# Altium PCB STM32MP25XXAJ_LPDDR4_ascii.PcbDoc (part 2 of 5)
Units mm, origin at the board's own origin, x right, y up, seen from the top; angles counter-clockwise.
Board outline 172 x 137 mm, 4 copper layers (Top Layer, Signal Layer 1, Signal Layer 2, Bottom Layer), stack 1.614 mm thick; 188 components, 294 nets, 1141 pads, 872 vias.
Unrouted connection lines stored in the file: 13.
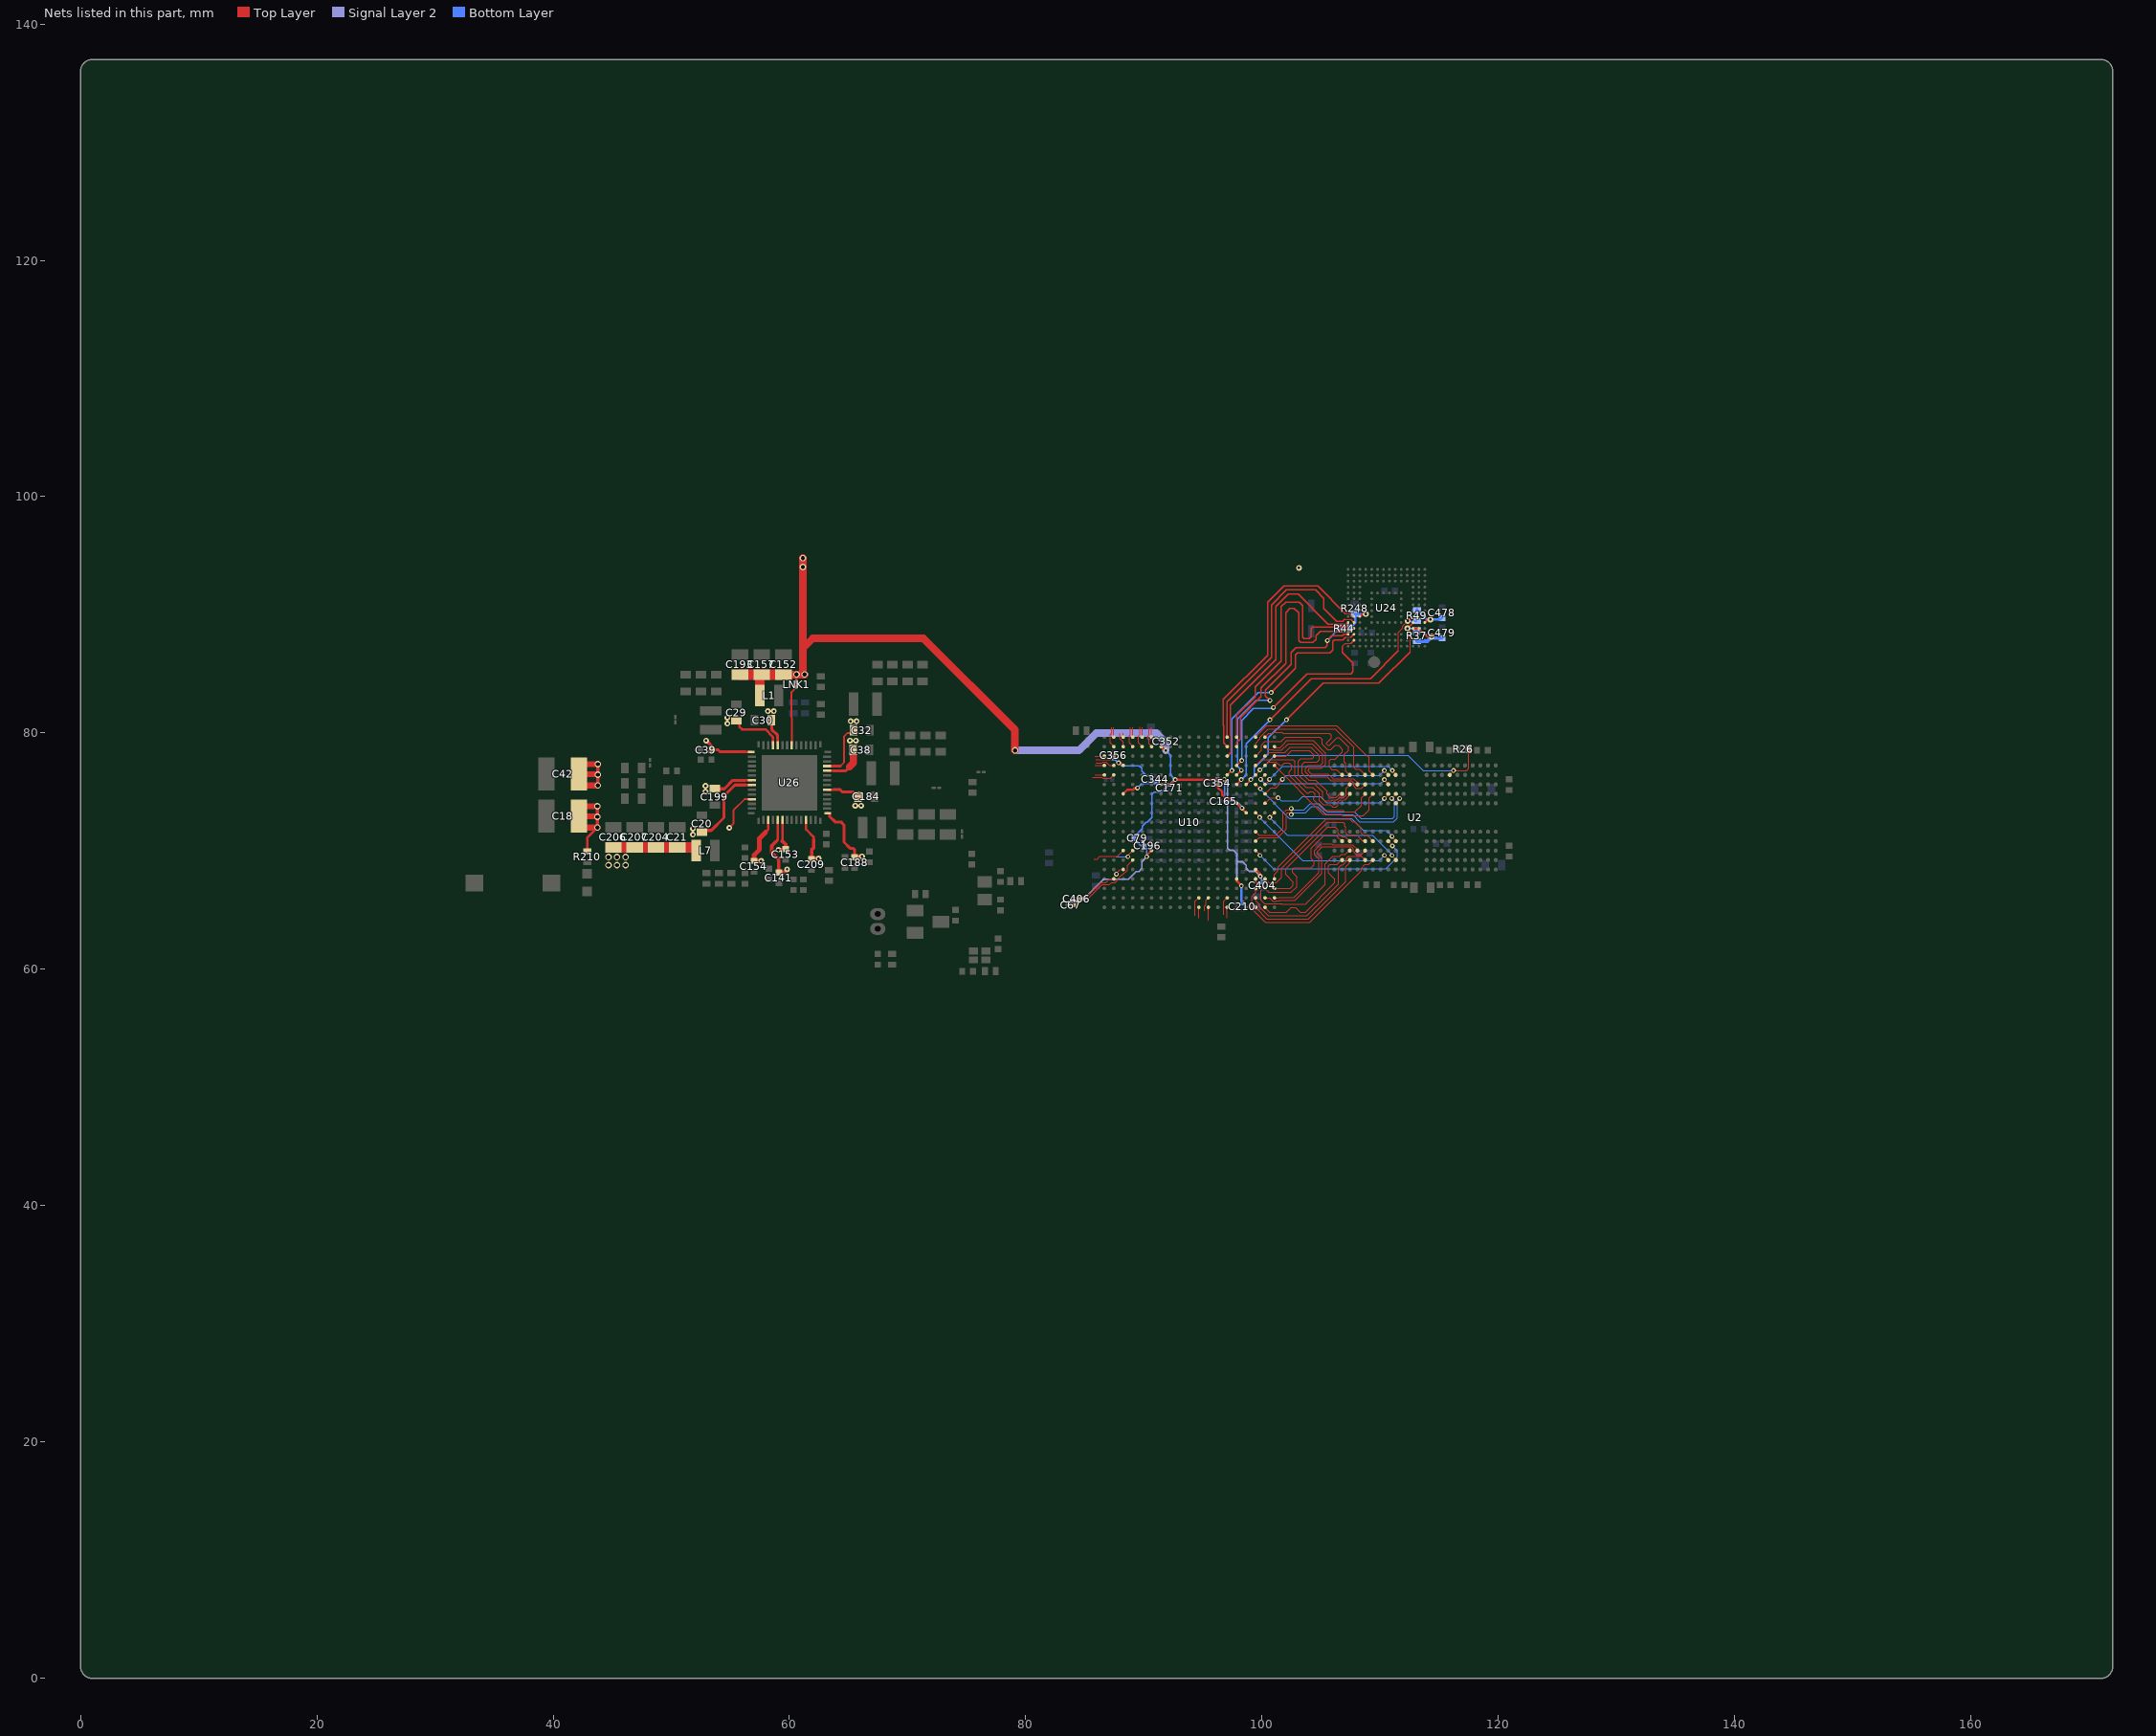
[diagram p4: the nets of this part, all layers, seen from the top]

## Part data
B2: library part MCD-03492, "Switch tactile, SPST-NO, 50mA, 12V, 6x3.8mm"
C18 C42: library part MCD-01796, "Capacitor, Tantalum, 100uF, 6V3, 40mR, +/-20%,  Type_B (3528 metric), T=1.9mm"
C19 C21 C152 C157 C186 C187 C193 C204 C206 C207: library part MCD-03139, "Capacitor, MLCC, 22uF, 10V, X5R, +/-20%, 0805, T=1,25mm"
C20 C29 C30 C32 C38 C184 C199: library part MCD-00099, "Capacitor, MLCC, 10uF, 10V, X5R, +/-10%, 0603, T=0,8mm"
C22 C23 C24 C26 C27 C28 C34 C35 C36 C37 C41 C183 C200 C202: library part MCD-00100, "Capacitor, MLCC, 22uF, 6V3, X5R, +/-20%, 0603, T=0,8mm"
C33: library part MCD-00011, "Capacitor, MLCC, 10nF, 16V, X7R, 10%, 0402, T=0.5mm"
C39 C43 C153 C154 C188: library part MCD-00095, "Capacitor, MLCC, 1uF, 25V, X5R, +/-10%, 0402, T=0.5mm"
C40: library part MCD-03140, "Capacitor, MLCC, 10uF, 6.3V, X5R, +/-20%, 0402, T=0.5mm"
C50 C51 C62 C63: library part MCD-01341, "Capacitor, MLCC, 10uF, 6V3, X5R, +/-20%, 0603, T=0.8mm"
C52 C53 C54 C55 C56 C57 C58 C59 C60 C61 C64 C65 C66 C68 C177 C182 C267 C479: library part MCD-00006, "Capacitor, MLCC, 100nF, 16V, X7R, +/-10%, 0402, T=0.5mm"
C67 C159 C163 C164 C166 C167 C168 C169 C173 C174 C175 C176 C191 C192 C195 C201 C360 C372 C377 C378 C380 C381 C382 C383 C386 C387 C388 C389 C390 C399 C400 C402: library part MCD-02377, "Capacitor, MLCC, 1uF, 6.3V, X5R, +/-20%, 0201, T=0,3mm"
C79: library part MCD-02235, "Capacitor, MLCC, 2.2uF, 10V, X5R,+/-10%, 0201, T=0.5mm"
C81 C86 C90 C92: library part MCD-00674, "Capacitor, MLCC, 6.8pF, 50V, NPO, +-0.25pF, 0402, T=0.5mm"
C87: library part MCD-00006, "Capacitor,100nF,16V,X7R,10%,0402"
C88: library part MCD-01823, "Capacitor, MLCC, 2.2uF, 6V3, X5R,+/-10%, 0402, T=0.5mm"
C91 C141 C142 C156 C189 C190 C208 C209 C217: library part MCD-01356, "Capacitor, MLCC, 4.7uF, 6V3, X5R, +/-20%, 0402, T=0.5mm"
C143 C161 C165 C171 C196 C210 C342 C344 C352 C353 C354 C355 C356 C357 C393 C404 C406 C407 C408 C409 C417: library part MCD-01535, "Capacitor, MLCC,100nF, 10V, X7R, +/-10%, 0201, T=0.3mm"
C155: library part MCD-02198, "Capacitor, MLCC, 10nF, 50V, X7R, +/-10%, 0402, T=0.5mm"
C180 C478 C481: library part MCD-02606, "Capacitor, MLCC, 2.2uF, 6.3V, X5R, +/-10%, 0402, T=0.5mm"
C384: library part MCD-01534, "Capacitor, MLCC, 4,7uF, 6V3, X5R, +/-20%, 0201, T=0.5mm"
CN12: library part MCD-00655, "Header 2 circuits, 1.25mm Pitch ,  Vertical, with Friction Lock"
D5: library part MCD-00034
D6: library part MCD-03280, "Diode, Schottky, Dual Common Cathode, 0V3, 300mA, 40V, SOT-23"
L1 L6: library part MCD-03143, "Inductor, 2.2uH, +/-20%, Itemp= 1700mA, Isat= 2400mA, 0R140, 0806, T=1mm"
L2 L4: library part MCD-03142, "Inductor, 0.68uH, +/-20%, Itemp= 3900mA, Isat= 5400mA, 0R031, 1008, T=1.2mm"
L3 L5 L7: library part MCD-03141, "Inductor, 0.68uH, +/-20%, Itemp= 3100mA, Isat= 4300mA, 0R043, 0806, T=1mm"
LD11: library part MCD-00588, "LED Green, 0603 SMD, Forward Voltage Typ=2V, Max=2.5V"
LNK1 LNK2 LNK4 LNK7 LNK8 LNK11: library part MCD-02777, "Track link on PCB 200um width for layout routing"
R2 R3 R46 R57 R59 R60 R64 R81 R197 R199: library part MCD-00052, "Resistor,0R,0402,5%,1/16W"
R26: library part MCD-00053, "Resistor, 10K, 0402, +/-1%, 1/16W"
R27 R37 R44 R49 R248 R272: library part MCD-00053, "Resistor,10K,0402,1%,1/16W"
R66: library part MCD-00058, "Resistor, 20R, 0402, +/-1%, 1/16W"
R67: library part MCD-00052, "Resistor, 0R, 0402, +/-5%, 1/16W"
R94: library part MCD-02253, "Resistor, 240R, 0201, +/-1%, 1/20W"
R112: library part MCD-02253, "Resistor,240R,0201,1%,1/20W"
R161 R162 R196: library part MCD-00417, "Resistor,200R,0402,1%,1/16W"
R210: library part MCD-00441, "Resistor,270R,0402,1%,1/16W"
R260 R261: library part MCD-00068, "Resistor,1K5,0402,1%,1/16W"
TP9: library part MCD-00074, "Test Point 1mm"
U2: library part MCD-04012, "Memory, SDRAM, 1V1, 16Gbit, 4266MHz"
U10: library part MCD-04441, "MPU, Dual Core ARM cortex-A35 64-bit + M33 32-bit,  808KB SRAM, With Crypto"
U24: library part MCD-02799, "Memory, eMMC, 4GB, 15nm ,WFBGA , 153 pins"
U26: library part MCD-03000, "STPMIC2"
X1: library part MCD-01479, "Crystal, 32.768kHz, 6pF, +/-20ppm, 80K, 2.05x1.2mm"
X2: library part MCD-02344, "Crystal, 40MHz, 6pF, +/-20ppm, 80R, 1.6x1.2mm"

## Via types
v1: diameter 0.55, hole 0.35, Top Layer to Bottom Layer, 349 vias
v2: diameter 0.4, hole 0.2, Top Layer to Bottom Layer, tented both sides, 257 vias
v3: diameter 0.5, hole 0.2, Top Layer to Bottom Layer, 189 vias
v4: diameter 0.4, hole 0.2, Top Layer to Bottom Layer, 77 vias

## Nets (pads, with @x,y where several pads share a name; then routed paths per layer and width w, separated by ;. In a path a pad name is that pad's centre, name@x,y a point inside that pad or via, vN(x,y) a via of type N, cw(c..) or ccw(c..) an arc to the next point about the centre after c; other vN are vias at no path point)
1V8: C67.2 C79.2 C152.2 C157.2 C165.2 C171.2 C193.2 C196.2 C210.2 C344.2 C352.2 C354.2 C356.2 C404.2 C406.2 C478.2 C479.2 L1.2 LNK1.2 R37.2 R44.2 R49.2 R248.2 U10.B7 U10.D3 U10.F7 U10.F8 U10.F13 U10.G3 U10.H15 U10.J16 U10.N6 U10.R17 U10.T2 U10.T15 U24.C6 U24.M4 U24.N4 U24.P3 U24.P5 | length 130.6
  Top Layer w0.09: v4(84.95,65.985) 85.023,65.985 86.393,67.355 86.772,67.355 87.073,67.656 U10.T2@87.444,67.656
  Top Layer w0.12: C67.2@84.1,65.4 84.575,65.875 C406.2@84.575,65.975 v4@84.95,65.975 ; v2(90.25,69.525) 90.25,69.65 U10.N6@90.65,70.05
  Top Layer w0.18: U24.C6@108.275,89.85 108.452,90.027 108.727,90.027 v3(108.775,90.075) ; U24.M4@112.775,88.85 U24.N4@113.275,88.85 113.75,88.375 U24.P3@113.775,88.375 ; U24.P3@113.775,88.35 113.975,88.15 v3(114.35,88.15) ; U24.P5@113.775,89.35 114.005,89.58 114.23,89.58 v3(114.25,89.6)
  Top Layer w0.2: LNK1.2@60.6,84.348 v1(60.6,84.95) ; v4(87.85,77.475) 87.888,77.437 88.036,77.437 88.223,77.25 U10.D3@88.25,77.25 ; U10.G3@88.25,74.85 88.612,75.212 89.093,75.212 89.193,75.312 89.412,75.312 v2(89.45,75.35) ; U10.F7@91.45,75.65 92.263,75.65 92.663,76.05 96.526,76.05 96.585,75.99 ; U10.B7@91.45,78.85 91.477,78.85 91.802,78.525 v4(91.85,78.525) ; U10.F13@96.245,75.65 96.585,75.99 ; U10.F13@96.25,75.65 96.25,75.393 96.638,75.006 96.638,74.749 96.913,74.474 97.426,74.474 U10.J16@98.65,73.25 ; v2(96.8,76.075) 96.762,76.037 96.632,76.037 96.585,75.99 ; U10.T15@97.85,67.65 97.85,67.475 v2(98.25,67.075) ; U10.R17@99.45,68.45 99.812,68.088 99.812,67.913 v2(99.85,67.875)
  Top Layer w0.64: C152.2@59.5,84.95 v1(60.6,84.95) v1(61.28,84.95) 61.142,85.088 61.142,87.175 ; v1(61.142,94.8) 61.142,87.175 ; v1@79.075,78.525 79.075,80.275 71.35,88 61.967,88 61.142,87.175
  Top Layer w0.8: L1.2@57.495,83.175 57.495,84.9 57.545,84.95 C157.2@57.65,84.95
  Top Layer w0.9: C193.2@55.8,84.95 C157.2@57.545,84.95 ; C157.2@57.65,84.95 C152.2@59.5,84.95
  Signal Layer 2 w0.12: v4(84.95,65.985) 86.592,67.627 88.693,67.627 89.341,68.275 89.575,68.275 89.8,68.5 89.8,68.506 89.81,68.516 89.81,69.085 v2(90.25,69.525)
  Signal Layer 2 w0.15: v2(96.8,76.075) 96.825,76.1 96.825,75.999 97.075,75.749 97.075,70.267 97.267,70.075 97.555,70.075 97.875,69.755 97.875,69.425 ; 97.875,69.452 97.875,69.097 ; v2@98.248,67.075 97.875,67.448 97.875,69.097 ; v2(99.85,67.875) 99.425,68.3 98.895,68.3 98.65,68.545 98.65,68.805 98.358,69.097 97.875,69.097
  Signal Layer 2 w0.64: v1@60.6,84.955 v1@61.28,84.955 ; v1(79.1,78.525) 84.507,78.525 85.97,79.988 91.047,79.988 91.85,79.185 v4(91.85,78.525)
  Bottom Layer w0.12: C356.2@87.45,77.85 87.8,77.5 v4@87.825,77.5 ; v4(87.85,77.475) 88.125,77.2 89.258,77.2 89.268,77.21 89.599,77.21 89.81,76.999 89.81,76.781 90.141,76.45 90.384,76.45 ; C79.2@89.15,71.125 89.29,70.985 89.29,70.898 89.572,70.616 89.599,70.616 89.74,70.475 90,70.475 90.243,70.232 v2@90.243,69.532 ; C79.2@89.15,71.175 89.29,71.315 89.29,71.365 89.856,71.931 89.856,72.116 90.176,72.435 90.269,72.435 90.69,72.856 90.69,74.815 90.865,74.99 91.503,74.99 92.023,75.51 92.11,75.51 C171.2@92.2,75.6 ; v2(89.45,75.35) 89.815,75.715 90.399,75.715 90.434,75.75 90.615,75.75 90.61,75.755 ; 90.4,76.45 90.384,76.45 ; C344.2@90.975,75.825 90.905,75.755 90.61,75.755 ; C344.2@91,75.739 92.061,75.739 C171.2@92.175,75.625 v2@92.6,76.05 ; v4@91.825,78.55 91.9,78.625 C352.2@91.9,79 ; v4(91.85,78.525) 92.25,78.125 92.25,76.45 92.6,76.1 v2@92.6,76.05 ; v2(92.65,76.05) v2@92.6,76.05 ; v2@92.65,76.1 v2@92.7,76.1 ; v2@92.671,76.012 v2@92.71,76.05 ; C354.2@96.225,76.05 96.25,76.075 v2(96.8,76.075) 96.84,76.036 96.84,74.43 96.95,74.32 96.95,74.3 C165.2@97.025,74.225 97.216,74.225 97.726,74.23 97.811,74.23 98.2,73.841 98.2,73.804 98.262,73.742 98.262,73.662 v2@98.25,73.65 ; 90.384,76.45 90.61,76.224 90.61,75.755
  Bottom Layer w0.15: v2(99.85,67.875) 99.95,67.775 C404.2@99.95,67.375
  Bottom Layer w0.2: v2@98.26,67.143 98.266,67.137 C210.2@98.266,65.523 ; R44.2@107.45,88.825 R44.2@107.425,88.85 107.9,89.325 R248.2@107.9,90.075 ; R248.2@107.85,90.075 R248.2@107.9,90.075 ; R248.2@107.9,90.1 R248.2@107.9,90.075 ; v3@108.8,90.075 v3(108.775,90.075) R248.2@107.9,90.075 ; R49.2@113.1,90.45 113.95,89.6 v3(114.25,89.6) 115.075,89.6 C478.2@115.2,89.725
  Bottom Layer w0.3: R37.2@113.125,87.775 113.975,87.775 v3(114.35,88.15) 114.418,88.15 114.543,88.025 C479.2@115.225,88.025
  other v1: 61.131,94.047
  other v2: 98.3,73.65
  other v3: 103.125,93.975
1V8_FB: LNK1.1 U26.35 | length 5.1
  Top Layer w0.15: U26.35@60.2,78.97 60.2,81.311 60.175,81.336 60.175,83.473 LNK1.1@60.6,83.898
3V3: C21.2 C154.2 C204.2 C206.2 C207.2 L7.2 U26.3 U26.53 | length 15.3
  Top Layer w0.15: v3(54.91,71.977) 55.262,72.329 55.262,73.465 56.197,74.4 U26.53@56.83,74.4 ; U26.53@56.62,74.369 56.919,74.369 U26.53@56.95,74.4
  Top Layer w0.21: 57.973,71.598 58.2,71.825 U26.3@58.2,72.63
  Top Layer w0.3: C154.2@56.975,69.175 C154.2@57,69.175 v3@57.585,69.175
  Top Layer w0.4: C154.2@57,69.175 57.014,69.189 57.014,69.685 57.46,70.131 57.46,71.085 57.973,71.598
  Top Layer w0.9: C206.2@45.087,70.323 C21.2@50.5,70.323 51.862,70.323 L7.2@51.887,70.298
  other v1: 44.687,68.823 45.412,68.823 46.137,68.823 44.687,69.498 45.412,69.498 46.137,69.498
  other v3: 57.61,69.175
5V_STLK: C18.1 C20.2 C29.2 C30.2 C32.2 C38.2 C39.2 C42.1 C153.2 C184.2 C188.2 C199.2 C209.2 R210.1 U26.6 U26.11 U26.15 U26.20 U26.24 U26.25 U26.38 U26.39 U26.43 U26.49 U26.50 | length 60.9
  Top Layer w0.15: 64.3,77.2 64.625,77.525 64.625,79.731 64.888,79.994 65.319,79.994 C32.2@65.425,80.1
  Top Layer w0.2: R210.1@42.887,69.97 42.887,71.138 v1(43.751,72.002)
  Top Layer w0.21: C29.2@55.525,81.05 55.762,80.813 55.762,80.513 55.975,80.3 57.964,80.3 58.6,79.664 U26.39@58.6,78.97 ; 56.275,75.6 U26.50@56.83,75.6 ; 56.275,76 U26.49@56.83,76 ; 56.275,78.4 U26.43@56.83,78.4 ; U26.38@59,78.97 59,79.525 ; 59.4,70.85 U26.6@59.4,72.63 ; U26.11@61.4,72.63 61.4,71.843 62.04,71.203 62.04,70.975 ; U26.15@63.17,73.2 U26.15@63.245,73.2 U26.15@63.285,73.2 ; U26.20@63.17,75.2 63.725,75.2 ; U26.24@63.17,76.8 63.725,76.8 ; U26.25@63.17,77.2 64.3,77.2
  Top Layer w0.25: C20.2@52.6,71.75 53.375,71.75 54.45,72.825 54.45,74.669 55.381,75.6 56.275,75.6 ; 53.195,79.125 53.199,79.125 53.345,78.979 53.345,78.685 C39.2@53.455,78.575 ; C39.2@53.505,78.575 53.975,78.575 54.15,78.4 56.275,78.4 ; C199.2@53.675,75.275 54.491,75.275 55.216,76 56.275,76 ; C30.2@58.425,81.075 58.494,81.006 58.494,80.308 59,79.802 59,79.525 ; 63.395,73.095 63.395,72.947 63.871,72.472 64.353,72.472 64.625,72.2 64.625,70.759 65.134,70.25 65.379,70.25 65.525,70.104 C188.2@65.525,69.55 ; 63.725,75.2 64.288,75.2 64.463,75.025 65.347,75.025 65.472,74.9 65.55,74.9 65.747,74.703 C184.2@65.747,74.625 ; 63.725,76.8 64.75,76.8 65.075,77.125
  Top Layer w0.3: v1(43.751,72.002) v1(43.751,72.902) v1(43.751,73.802) ; v1(43.776,75.565) v1(43.776,76.465) v1(43.776,77.365) ; v3@52.944,79.376 53.195,79.125 ; v3(59.065,70.11) 59.675,70.11 59.674,70.111 59.674,70.576 59.4,70.85 ; C209.2@61.85,69.38 C209.2@61.875,69.38 ; 62.04,70.975 62.04,70.269 61.875,70.104 C209.2@61.875,69.38 ; v3(62.46,69.38) C209.2@61.875,69.38 ; C188.2@65.525,69.55 v3(66.135,69.55)
  Top Layer w0.5: C18.1@42.187,72.049 42.235,72.002 v1(43.751,72.002) ; C18.1@42.187,72.961 43.679,72.961 43.737,72.902 v1(43.751,72.902) ; C42.1@42.187,75.612 42.235,75.565 v1(43.776,75.565) ; C42.1@42.187,76.523 43.704,76.523 43.762,76.465 v1(43.776,76.465) ; C18.1@42.246,73.802 v1(43.751,73.802) ; C42.1@42.246,77.365 v1(43.776,77.365)
  Top Layer w0.6: 65.075,77.125 65.4,77.45 C38.2@65.4,78.175
  other v3: 51.825,71.4 51.825,71.9 65.575,73.85 66.075,73.85 52.9,75.025 52.9,75.525 52.95,79.348 65.125,79.35 65.625,79.35 54.75,80.8 65.175,81 65.675,81 54.75,81.3 58.175,81.85 58.675,81.85
5V_VCONN: C141.1 U26.5 | length 5.7
  Top Layer w0.21: 58.877,70.828 59,70.95 U26.5@59,72.63
  Top Layer w0.3: 58.877,70.828 58.51,70.46 58.51,69.865 59.1,69.275 C141.1@59.1,68.2 59.539,68.2 v3(59.8,68.46)
ANA0: U10.V14 | length 1.6
  Top Layer w0.1: 96.75,64.622 96.75,65.75 U10.V14@97.05,66.05
ANA1: U10.W14 | length 0.9
  Top Layer w0.1: 97.05,64.356 U10.W14@97.05,65.25
BOOT0: U10.N3 | length 2.8
  Top Layer w0.1: 85.77,69.336 86.045,69.336 86.259,69.55 87.75,69.55 U10.N3@88.25,70.05
BOOT1: U10.N4 | length 1.6
  Top Layer w0.1: v2@88.645,69.65 U10.N4@89.045,70.05
  Bottom Layer w0.1: 87.652,69.525 v2(88.645,69.525)
BOOT2: U10.R3 | length 0.7
  Top Layer w0.09: v4@87.669,68.169 87.95,68.45 U10.R3@88.25,68.45
  other v4: 87.675,68.05
BOOT3: U10.P4 | length 5.3
  Top Layer w0.09: 85.386,66.079 86.472,67.165 87.077,67.165 87.267,67.355 87.572,67.355 87.775,67.557 87.775,67.632 88.111,67.969 88.186,67.969 88.592,68.375 88.592,68.792 U10.P4@89.05,69.25
COMBOPHY_RX1N: U10.W12 | length 1.1
  Top Layer w0.09: 95.45,64.15 U10.W12@95.45,65.25
COMBOPHY_RX1P: U10.V12 | length 1.2
  Top Layer w0.09: 95.15,64.945 95.15,65.372 95.236,65.459 95.236,65.841 U10.V12@95.445,66.05
COMBOPHY_TX1N: U10.W11 | length 0.9
  Top Layer w0.09: 94.645,64.356 94.645,65.245 U10.W11@94.65,65.25
COMBOPHY_TX1P: U10.V11 | length 1.6
  Top Layer w0.09: 94.335,64.562 94.335,65.74 U10.V11@94.645,66.05
CSI_CKN: U10.C2 | length 1.6
  Top Layer w0.09: 85.938,77.748 87.148,77.748 U10.C2@87.45,78.05
CSI_CKP: U10.C1 | length 0.8
  Top Layer w0.09: 85.875,78.05 U10.C1@86.65,78.05
CSI_D0N: U10.E1 | length 0.8
  Top Layer w0.09: 85.875,76.45 U10.E1@86.65,76.45
CSI_D0P: U10.E2 | length 2
  Top Layer w0.09: 85.639,76.247 86.435,76.247 86.528,76.155 87.155,76.155 U10.E2@87.45,76.45
CSI_D1N: U10.D2 | length 1.7
  Top Layer w0.09: 85.92,77.452 86.435,77.452 86.528,77.545 86.794,77.545 87.089,77.25 U10.D2@87.45,77.25
CSI_D1P: U10.D1 | length 0.8
  Top Layer w0.09: 85.875,77.25 U10.D1@86.65,77.25
DDR_CA0: U2.H2 U10.J17 | length 13.3
  Top Layer w0.09: U10.J17@99.45,73.25 99.8,72.9 v2(99.8,72.85) ; v4@110.35,69.625 110.35,69.6 110.675,69.275 U2.H2@110.675,69.25
  Bottom Layer w0.09: v2(99.8,72.85) 103.45,69.2 109.9,69.2 v4(110.35,69.65)
DDR_CA1: U2.J2 U10.J19 | length 13
  Top Layer w0.09: v2@100.533,72.733 v2(100.65,72.85) U10.J19@101.05,73.25 ; v4(111,69.65) 111,69.625 111.325,69.3 U2.J2@111.325,69.25
  Bottom Layer w0.09: v2(100.65,72.85) 102.155,71.345 109.338,71.345 111,69.683 v4(111,69.65)
DDR_CA2: U2.H9 U10.H18 | length 11.4
  Top Layer w0.09: U10.H18@100.255,74.05 100.255,74.055 100.717,74.517 v2(101.354,74.517) ; v4(110.35,74.45) 110.675,74.775 U2.H9@110.675,74.85
  Bottom Layer w0.09: v2(101.354,74.517) 101.6,74.272 103.084,74.272 103.425,74.612 104.938,74.612 105.445,74.105 110.005,74.105 v4(110.35,74.45)
DDR_CA3: U2.H10 U10.E18 | length 11.9
  Top Layer w0.09: v2(99.875,76.075) U10.E18@100.25,76.45 ; v4(110.35,76.05) 110.35,76.012 110.675,75.688 U2.H10@110.675,75.65
  Bottom Layer w0.09: v2(99.875,76.075) 100.245,75.705 110.032,75.705 110.35,76.023 v4(110.35,76.05)
DDR_CA4: U2.H11 U10.G18 | length 11.5
  Top Layer w0.09: U10.G18@100.25,74.858 100.258,74.858 100.75,75.35 101.167,75.35 101.442,75.625 101.442,75.792 v2(101.725,76.075) ; v4(110.35,76.825) 110.35,76.775 U2.H11@110.65,76.475
  Bottom Layer w0.09: v2(101.725,76.075) 102.045,76.395 109.945,76.395 ; 109.92,76.395 v4(110.35,76.825)
DDR_CA5: U2.J11 U10.F18 | length 12.1
  Top Layer w0.09: U10.F18@100.25,75.65 100.625,76.025 v2(100.625,76.075) ; v4(111.025,76.825) 111.325,76.525 U2.J11@111.325,76.45
  Bottom Layer w0.09: v2(100.625,76.075) 101.72,77.17 110.705,77.17 ; 110.68,77.17 v4(111.025,76.825)
DDR_CKE: U2.J4 U10.F17 | length 13.9
  Top Layer w0.09: U10.F17@99.45,75.65 99.462,75.65 99.838,75.275 v2(99.85,75.275) ; v4(111,71.25) 111,71.175 U2.J4@111.325,70.85
  Bottom Layer w0.09: v2(99.85,75.275) 99.85,75.217 102.312,72.755 107.57,72.755 108.576,71.749 110.501,71.749 v4(111,71.25)
DDR_CLK_N: U2.J9 U10.L17 | length 16.6
  Top Layer w0.09: U10.L17@99.45,71.65 99.748,71.352 101.177,71.352 101.79,71.965 101.79,73.253 102.037,73.5 102.291,73.5 102.391,73.6 v4(102.475,73.6) ; v4@110.95,74.476 U2.J9@111.325,74.85
  Bottom Layer w0.09: v4@102.458,73.617 102.542,73.617 102.677,73.482 103.557,73.482 104.101,74.026 104.809,74.026 105.51,73.325 107.804,73.325 107.95,73.179 107.95,73.173 108.373,72.75 111.042,72.75 111.2,72.908 111.2,74.225 v4@110.972,74.453
  other v4: 110.975,74.45
DDR_CLK_P: U2.J8 U10.M17 | length 16.9
  Top Layer w0.09: U10.M17@99.45,70.85 99.762,71.162 101.341,71.162 101.777,71.598 ; 101.777,71.598 102.04,71.861 102.04,73.15 102.133,73.242 ; 102.143,73.25 102.325,73.25 v4(102.475,73.1) ; U2.J8@111.3,74.025 111.65,74.375 v4(111.65,74.45)
  Bottom Layer w0.09: v4@102.557,73.122 102.573,73.122 102.683,73.232 103.66,73.232 104.205,73.776 104.705,73.776 105.406,73.075 107.7,73.075 ; 107.697,73.072 108.269,72.5 111.146,72.5 111.45,72.804 111.45,74.25 v4(111.65,74.45)
DDR_CS: U2.H4 U10.N17 | length 14.8
  Top Layer w0.09: U10.N17@99.45,70.05 v4@99.85,69.65 ; U2.H4@110.675,70.85 110.675,70.813 111.025,70.462 v4(111.025,70.45) v4@111.025,70.425
  Bottom Layer w0.09: v4(99.825,69.65) 100.975,68.5 110.476,68.5 111.452,69.476 111.452,70.023 v4(111.025,70.45)
DDR_DQ0: U2.B2 U10.W18 | length 10.4
  Top Layer w0.09: U10.W18@100.25,65.25 100.653,64.847 102.047,64.847 102.443,65.243 102.827,65.243 103.223,64.847 103.679,64.847 106.16,67.328 106.16,67.612 105.635,68.137 105.635,68.76 105.758,68.883 106.359,68.883 106.726,69.25 U2.B2@106.775,69.25
DDR_DQ1: U2.C2 U10.W17 | length 11.3
  Top Layer w0.09: U10.W17@99.45,65.25 99.45,65.22 100.403,64.267 103.92,64.267 107.093,67.441 107.093,68.669 107.42,68.996 107.42,69.233 U2.C2@107.431,69.244
DDR_DQ2: U2.E2 U10.V17 | length 13.3
  Top Layer w0.09: U10.V17@99.45,66.05 99.45,65.811 99.8,65.461 99.8,65.283 100.526,64.557 103.8,64.557 106.45,67.207 106.45,68.578 106.713,68.842 106.827,68.842 107.1,69.114 107.1,69.378 107.282,69.56 108.418,69.56 U2.E2@108.725,69.253
DDR_DQ3: U2.F2 U10.U17 | length 14.9
  Top Layer w0.09: U10.U17@99.45,66.85 99.45,66.482 99.153,66.185 99.153,65.105 100.281,63.977 104.04,63.977 108.399,68.336 108.399,68.563 108.704,68.868 109.001,68.868 U2.F2@109.375,69.241
DDR_DQ4: U2.F4 U10.T19 | length 11.9
  Top Layer w0.09: U10.T19@101.05,67.65 101.05,68.033 101.345,68.328 101.345,68.417 101.36,68.432 101.36,68.687 105.408,72.735 107.387,72.735 107.644,72.478 107.853,72.478 108.385,71.946 108.385,71.552 108.596,71.34 108.885,71.34 U2.F4@109.375,70.85
DDR_DQ5: U2.E4 U10.T18 | length 12.2
  Top Layer w0.09: U10.T18@100.25,67.646 100.561,67.334 101.208,67.334 101.369,67.496 ; 101.375,67.5 101.65,67.775 101.65,68.567 105.528,72.445 106.88,72.445 106.995,72.33 106.995,72.138 107.085,72.048 107.085,71.552 107.296,71.34 108.033,71.34 108.473,70.9 108.675,70.9 U2.E4@108.725,70.85
DDR_DQ6: U2.C4 U10.U19 | length 10.9
  Top Layer w0.09: U10.U19@101.05,66.83 U10.U19@101.06,66.84 ; U10.U19@101.05,66.85 101.055,66.855 102.387,66.855 102.641,67.109 102.641,67.399 102.023,68.017 102.023,68.527 105.537,72.042 ; 105.535,72.042 105.537,72.042 ; 106.17,72.042 105.537,72.042 ; 106.171,72.042 106.44,71.773 106.44,71.52 106.735,71.225 107.052,71.225 U2.C4@107.425,70.85
DDR_DQ7: U2.B4 U10.U18 | length 11.4
  Top Layer w0.09: U10.U18@100.25,66.85 100.564,66.536 102.478,66.536 102.931,66.989 102.931,67.819 102.577,68.173 102.577,68.46 102.718,68.601 104.174,68.601 104.4,68.827 104.4,69.124 104.147,69.377 104.147,70.242 105.232,71.327 106.272,71.327 106.749,70.85 U2.B4@106.775,70.85
DDR_DQ8: U2.B11 U10.C17 | length 12.7
  Top Layer w0.09: U10.C17@99.45,78.05 99.95,78.55 99.95,78.975 100.25,79.275 101.592,79.275 101.981,79.664 104.886,79.664 105.1,79.45 105.1,79.025 105.527,78.598 105.825,78.598 106.171,78.944 106.455,78.944 106.79,78.608 106.79,78.413 106.169,77.792 105.833,77.792 105.691,77.65 105.691,77.254 105.691,77.122 105.897,76.916 106.302,76.916 U2.B11@106.768,76.45
DDR_DQ9: U2.C11 U10.A18 | length 12
  Top Layer w0.09: U10.A18@100.25,79.65 100.575,79.975 100.873,79.975 100.943,80.045 101.693,80.045 101.763,79.975 105.703,79.975 105.863,79.815 105.863,79.566 105.477,79.18 105.477,79.058 105.563,78.972 105.698,78.972 106.35,79.625 106.505,79.625 107.325,78.805 107.325,78.525 106.973,78.173 106.973,77.561 107.095,77.44 107.095,76.778 U2.C11@107.423,76.45
DDR_DQ10: U2.E11 U10.B17 | length 12.7
  Top Layer w0.09: U10.B17@99.45,78.85 99.45,79.12 99.841,79.511 99.841,79.651 100.525,80.335 106.205,80.335 107.755,78.785 107.755,77.118 107.942,76.93 108.246,76.93 U2.E11@108.725,76.451
DDR_DQ11: U2.F11 U10.A17 | length 12.7
  Top Layer w0.09: U10.A17@99.45,79.654 99.45,79.67 100.405,80.625 106.325,80.625 108.7,78.25 ; 108.702,78.252 109.045,77.909 109.045,76.78 U2.F11@109.375,76.45
DDR_DQ12: U2.F9 U10.D19 | length 11.4
  Top Layer w0.09: U10.D19@101.05,77.25 105.154,73.146 106.718,73.146 106.839,73.025 108.563,73.025 109.047,73.51 109.047,74.523 U2.F9@109.375,74.85
DDR_DQ13: U2.E9 U10.D18 | length 12.8
  Top Layer w0.09: U10.D18@100.25,77.25 100.545,77.545 101.177,77.545 101.472,77.25 101.7,77.25 101.914,77.464 102.302,77.464 102.505,77.261 102.505,76.95 102.3,76.745 102.3,76.41 103.785,74.925 103.95,74.925 104.053,75.028 104.281,75.028 104.467,74.842 104.467,74.617 104.359,74.509 104.359,74.351 105.274,73.436 106.838,73.436 106.959,73.315 107.841,73.315 ; 107.85,73.325 108.397,73.872 108.397,74.523 U2.E9@108.725,74.85
DDR_DQ14: U2.C9 U10.D17 | length 11.6
  Top Layer w0.09: U10.D17@99.45,77.25 99.954,77.754 102.606,77.754 102.795,77.565 102.795,76.325 103.703,75.417 104.302,75.417 104.855,74.865 104.855,74.266 105.16,73.96 105.76,73.96 105.988,73.733 105.989,73.733 105.992,73.73 106.257,73.73 106.445,73.918 106.445,74.183 106.622,74.36 107.045,74.36 107.375,74.69 107.375,74.798 U2.C9@107.425,74.85
DDR_DQ15: U2.B9 U10.C18 | length 12.5
  Top Layer w0.09: U10.C18@100.25,78.05 100.552,78.352 101.927,78.352 102.385,78.81 104.105,78.81 104.848,78.067 104.848,77.739 104.65,77.54 103.577,77.54 103.375,77.339 103.375,76.565 103.943,75.997 104.542,75.997 105.482,75.057 105.482,74.818 105.76,74.54 106.253,74.54 106.54,74.827 106.751,74.827 U2.B9@106.775,74.85
DDR_DQM0: U2.C3 U10.T17 | length 12.5
  Top Layer w0.09: U10.T17@99.45,67.65 99.45,67.374 99.915,66.909 99.915,65.835 100.205,65.545 101.635,65.545 101.646,65.533 103.678,65.533 105.335,67.19 105.335,68.899 105.996,69.56 106.557,69.56 106.715,69.719 107.027,69.719 107.359,70.05 U2.C3@107.425,70.05
DDR_DQM1: U2.C10 U10.C19 | length 13
  Top Layer w0.09: U10.C19@101.042,78.045 101.725,78.045 102.03,78.045 102.505,78.52 103.985,78.52 104.371,78.134 104.371,77.946 104.255,77.83 103.284,77.83 103.085,77.631 103.085,76.445 103.823,75.707 104.422,75.707 105.145,74.985 105.145,74.386 105.28,74.25 105.886,74.25 105.996,74.36 106.367,74.36 106.547,74.54 106.91,74.54 107.106,74.736 107.106,75.329 U2.C10@107.425,75.65
DDR_DQS0_N: U2.E3 U10.V18 | length 12.6
  Top Layer w0.09: U10.V18@100.25,66.05 100.633,66.05 100.928,65.755 101.168,65.755 101.213,65.8 101.448,65.8 101.498,65.85 102.798,65.85 105.045,68.097 105.045,69.449 104.687,69.806 104.687,69.966 105.081,70.36 107.553,70.36 107.735,70.179 107.735,69.952 107.946,69.74 108.415,69.74 U2.E3@108.725,70.05
DDR_DQS0_P: U2.D3 U10.V19 | length 10.8
  Top Layer w0.09: U10.V19@101.05,66.05 101.344,66.05 101.394,66.1 102.694,66.1 104.795,68.2 104.795,69.345 104.437,69.703 104.437,70.069 104.978,70.61 105.912,70.61 ; 105.913,70.61 105.915,70.61 105.985,70.54 107.655,70.54 108.075,70.12 U2.D3@108.075,70.05
DDR_DQS1_N: U2.E10 U10.B18 | length 14.3
  Top Layer w0.09: U10.B18@100.25,78.85 100.515,78.585 100.912,78.585 100.947,78.55 101.655,78.55 102.205,79.1 104.225,79.1 105.138,78.187 105.138,77.464 104.925,77.25 103.9,77.25 103.665,77.015 103.665,76.686 104.063,76.287 105.493,76.287 105.819,75.962 ; 105.82,75.96 107.553,75.96 107.75,75.763 107.75,75.522 107.942,75.33 108.405,75.33 U2.E10@108.724,75.65 ; U2.E10@108.764,75.687 U2.E10@108.801,75.649
DDR_DQS1_P: U2.D10 U10.B19 | length 12.5
  Top Layer w0.09: U10.B19@101.05,78.85 101.107,78.85 101.192,78.765 101.516,78.765 101.797,79.046 ; 101.797,79.046 102.1,79.35 104.329,79.35 105.388,78.29 105.388,77.361 105.028,77 104.004,77 103.915,76.912 103.915,76.789 104.167,76.537 105.597,76.537 105.924,76.21 ; 105.925,76.211 105.996,76.14 107.732,76.14 ; 107.733,76.133 108.075,75.792 U2.D10@108.075,75.65
DDR_RESETN: R26.2 U2.T11 U10.E17 | length 21.6
  Top Layer w0.09: U10.E17@99.449,76.451 99.449,76.474 99.825,76.85 v2(99.825,76.875)
  Top Layer w0.1: U2.T11@115.875,76.45 v4@116.225,76.8 ; v4@116.26,76.835 117.322,76.835 117.5,77.013 117.5,78.6 R26.2@117.475,78.625 ; R26.2@117.27,78.84 R26.2@117.27,78.94
  Bottom Layer w0.1: v2(99.825,76.875) 99.85,76.875 101.1,78.125 112.35,78.125 113.65,76.825 v4(116.2,76.825) ; v4@116.225,76.75 v4@116.225,76.825
DSI_CKN: U10.B4 | length 1.8
  Top Layer w0.09: 88.86,80.463 88.86,79.877 88.755,79.772 88.755,79.145 U10.B4@89.05,78.85
DSI_CKP: U10.A4 | length 0.8
  Top Layer w0.09: U10.A4@89.05,79.65 89.05,80.464
DSI_D0N: U10.A6 | length 0.8
  Top Layer w0.1: U10.A6@90.65,79.65 90.65,80.443
DSI_D0P: U10.B6 | length 1.7
  Top Layer w0.1: 90.425,80.391 90.425,79.849 90.35,79.774 90.35,79.526 90.425,79.451 90.425,79.075 U10.B6@90.65,78.85
DSI_D1N: U10.A5 | length 0.8
  Top Layer w0.09: U10.A5@89.85,79.65 89.85,80.464
DSI_D1P: U10.B5 | length 1.8
  Top Layer w0.09: 89.66,80.481 89.66,79.877 89.555,79.772 89.555,79.145 U10.B5@89.85,78.85
DSI_D2N: U10.A3 | length 0.3
  Top Layer w0.09: U10.A3@88.25,79.65 88.25,79.978
DSI_D2P: U10.B3 | length 1.2
  Top Layer w0.09: 87.954,79.974 87.954,79.527 88.25,79.231 U10.B3@88.25,78.85
DSI_D3N: U10.A2 | length 0.8
  Top Layer w0.09: U10.A2@87.45,79.65 87.45,80.464
DSI_D3P: U10.B2 | length 1.8
  Top Layer w0.09: 87.258,80.464 87.258,79.966 87.152,79.86 87.152,79.148 U10.B2@87.45,78.85
eMMC.SDMMC2_CK: R49.1 U10.F15 U24.M6 | length 24.2
  Top Layer w0.09: 111.525,86.961 111.525,88.454 111.525,88.502 111.823,88.8 111.825,88.8 111.905,88.88 111.905,89.03 112.325,89.45 v3(112.325,89.475)
  Top Layer w0.11: U10.F15@97.85,75.65 97.85,75.655 v2(98.245,76.05) ; v4(100.675,81.125) 104.15,84.6 109.164,84.6 111.525,86.961 ; v3(112.325,89.475) 112.4,89.475 U24.M6@112.775,89.85
  Bottom Layer w0.11: v2(98.245,76.05) 98.635,76.44 98.635,79.081 v4@100.7,81.146 ; v3@112.35,89.45 113.05,89.45 R49.1@113.1,89.5
eMMC.SDMMC2_CMD: R37.1 U10.F16 U24.M5 | length 23.4
  Top Layer w0.09: v3(112.3,88.85) 112.3,88.83 112.525,88.605 112.525,86.875
  Top Layer w0.11: U10.F16@98.645,75.65 v2@99.045,76.05 ; v4(102.075,81.125) 105.175,84.225 109.875,84.225 112.525,86.875 ; v3(112.3,88.85) 112.3,88.863 112.775,89.338 U24.M5@112.775,89.35
  Bottom Layer w0.11: v2(99.05,76.05) 99.355,76.355 99.355,77.074 100.533,78.252 100.533,79.593 v4@102.083,81.142 ; v3@112.286,88.836 v3(112.3,88.85) 112.925,88.85 R37.1@113.125,88.65
eMMC.SDMMC2_D0: R44.1 U10.E15 U24.A3 | length 20.7
  Top Layer w0.11: U10.E15@97.85,76.45 v2(98.25,76.85) ; v4(100.675,82.75) 100.275,83.15 100.275,83.6 102.475,85.8 102.475,86.828 102.864,87.217 105.323,87.217 105.507,87.401 105.507,87.807 v4(105.525,87.825) ; v4@105.508,87.833 105.904,88.229 106.797,88.229 106.918,88.35 U24.A3@107.275,88.35
  Bottom Layer w0.11: v2(98.25,76.85) 97.909,77.191 97.909,81.18 99.504,82.775 v4@100.675,82.775 ; v4(105.525,87.825) 105.525,87.85 R44.1@106.525,88.85
eMMC.SDMMC2_D1: U10.A15 U24.A4 | length 22.1
  Top Layer w0.11: U10.A15@97.85,79.65 97.85,81.494 99.427,83.071 99.427,83.896 101.62,86.089 101.62,90.695 101.997,91.073 103.155,91.073 103.425,90.803 103.425,88.125 103.55,88 104,88 104.15,88.15 104.15,88.85 104.284,88.984 107.141,88.984 U24.A4@107.275,88.85
eMMC.SDMMC2_D2: U10.C14 U24.A5 | length 22
  Top Layer w0.11: U10.C14@97.05,78.05 97.355,78.355 97.355,79.776 97.327,79.804 97.327,82.377 101.172,86.222 101.172,90.705 102.209,91.741 103.049,91.741 105.583,89.207 107.126,89.207 U24.A5@107.269,89.35
eMMC.SDMMC2_D3: U10.D15 U24.B2 | length 18.7
  Top Layer w0.09: 106.798,87.348 107.05,87.6 107.525,87.6
  Top Layer w0.11: U10.D15@97.85,77.25 v4(98.275,77.675) ; v4(100.95,82.15) 103.804,85.004 107.523,85.004 107.699,85.18 107.699,85.929 106.798,86.831 106.798,87.348 ; 107.525,87.6 U24.B2@107.775,87.85
  Bottom Layer w0.11: v4(98.275,77.675) 98.275,81.068 99.274,82.067 v4@100.872,82.067
eMMC.SDMMC2_D4: U10.E14 U24.B3 | length 19.4
  Top Layer w0.09: 107.095,88.1 107.525,88.1
  Top Layer w0.11: U10.E14@97.05,76.45 v4@97.515,76.915 ; v4(100.775,83.425) 102.825,85.475 102.825,86.6 103.006,86.781 105.745,86.781 106,87.036 106,87.75 106.104,87.853 106.848,87.853 107.095,88.1 ; 107.525,88.1 U24.B3@107.775,88.35
  Bottom Layer w0.11: v4(97.45,76.825) 97.45,81.2 99.675,83.425 v4(100.775,83.425) v4@100.8,83.425
eMMC.SDMMC2_D5: U10.B15 U24.B4 | length 22.2
  Top Layer w0.09: 106.8,88.6 107.525,88.6
  Top Layer w0.11: U10.B15@97.85,78.85 97.85,79.2 98.155,79.505 98.155,81.315 99.925,83.085 99.925,83.825 102,85.9 102,90.187 102.359,90.546 102.714,90.546 103.09,90.17 103.09,87.844 103.284,87.65 104.3,87.65 104.575,87.925 104.575,88.225 104.948,88.598 106.798,88.598 ; 107.525,88.6 U24.B4@107.775,88.85
eMMC.SDMMC2_D6: U10.A14 U24.B5 | length 22
  Top Layer w0.09: 107.05,89.6 107.525,89.6
  Top Layer w0.11: U10.A14@97.05,79.65 97.05,80.194 ; 97.05,80.2 97.05,82.65 100.8,86.4 100.8,90.842 102.065,92.107 104.526,92.107 105.225,91.408 105.225,90.534 106.314,89.445 106.818,89.445 106.973,89.6 107.05,89.6 ; 107.525,89.6 U24.B5@107.775,89.35
eMMC.SDMMC2_D7: U10.B14 U24.B6 | length 22.9
  Top Layer w0.09: 107.05,90.1 107.382,90.1 107.617,89.865
  Top Layer w0.11: U10.B14@97.05,78.85 96.745,79.155 96.745,80.613 96.704,80.654 96.704,82.829 100.458,86.583 100.458,91.052 101.835,92.43 104.718,92.43 107.048,90.1 ; 107.617,89.865 107.76,89.865 U24.B6@107.775,89.85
